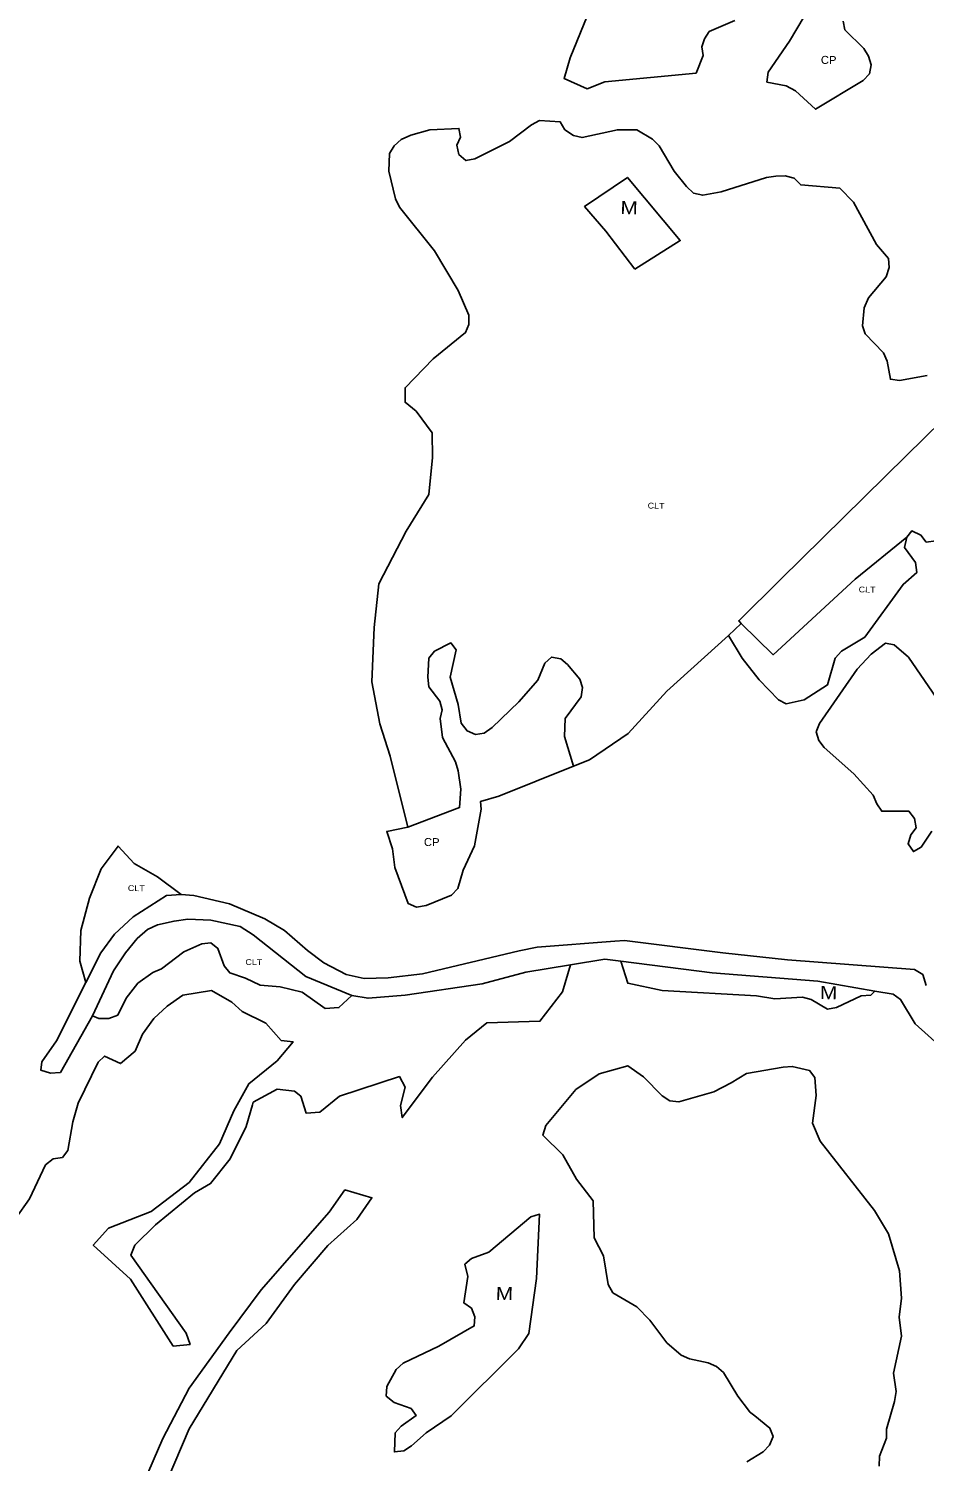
# Model space of a CAD drawing. Extents: x 713589 to 726391, y 7177764 to 7191819.
# Drawn here: x 716445 to 717161, y 7179057 to 7180202 of the extents above; entities that cross this region are included whole.
import ezdxf
from ezdxf.enums import TextEntityAlignment as Align

# ---------------------------------------------------------------- set-up
doc = ezdxf.new("R2010")
doc.units = 0
doc.header["$LTSCALE"] = 2.6
doc.layers.add('63', color=7, linetype='Continuous', lineweight=25)

msp = doc.modelspace()

# ---------------------------------------------------------------- linework, layer by layer
at = {"layer": '63'}
msp.add_line((717003.94, 7179716.98), (717014.24, 7179726.64), dxfattribs=at)
for points in [[(717009.07, 7180208.54), (716988.67, 7180199.99), (716984.72, 7180194.07), (716982.74, 7180187.48), (716983.73, 7180180.57), (716978.13, 7180166.59), (716905.26, 7180159.55), (716891.06, 7180153.97), (716872.6, 7180162.25), (716877.58, 7180178.73), (716891.16, 7180212.03)], [(717064.36, 7180211.82), (717052.84, 7180192.08), (717035.72, 7180167.4), (717034.64, 7180159.41), (717050.07, 7180156.31), (717057.64, 7180152.54), (717073.53, 7180137.76), (717111.73, 7180160.81), (717116.67, 7180166.07), (717117.99, 7180173.31), (717116.01, 7180180.22), (717112.07, 7180186.15), (717096.93, 7180201.28), (717095.62, 7180208.2)], [(717162.68, 7179924.84), (717140.63, 7179920.89), (717133.39, 7179921.88), (717130.76, 7179936.36), (717127.8, 7179942.94), (717113.32, 7179958.08), (717111.02, 7179964.67), (717112.42, 7179978.94), (717115.96, 7179987.04), (717130.11, 7180003.82), (717132.42, 7180011.06), (717131.76, 7180018.3), (717122.22, 7180029.49), (717103.8, 7180063.39), (717092.94, 7180074.58), (717061.68, 7180077.22), (717056.41, 7180082.48), (717049.17, 7180084.46), (717041.93, 7180084.13), (717034.37, 7180083.14), (716998.17, 7180071.63), (716983.36, 7180069), (716976.12, 7180070.65), (716970.52, 7180075.92), (716960.65, 7180088.09), (716948.48, 7180108.5), (716943.22, 7180113.76), (716930.72, 7180121.34), (716915.25, 7180121.34), (716886.95, 7180115.09), (716880.04, 7180116.74), (716873.13, 7180121.35), (716869.51, 7180127.6), (716853.06, 7180128.59), (716846.47, 7180125.3), (716829.03, 7180111.81), (716801.39, 7180097.99), (716794.15, 7180096.68), (716788.55, 7180101.62), (716786.91, 7180108.86), (716789.87, 7180115.44), (716788.56, 7180122.35), (716765.19, 7180121.36), (716750.05, 7180117.09), (716742.49, 7180113.47), (716736.89, 7180108.54), (716732.94, 7180102.28), (716732.61, 7180088.13), (716737.87, 7180066.09), (716741.16, 7180059.5), (716769.12, 7180024.62), (716787.88, 7179992.69), (716796.43, 7179972.95), (716796.43, 7179965.71), (716793.88, 7179959.1), (716767.99, 7179938.1), (716745.52, 7179915.05), (716745.5, 7179903.51), (716754.4, 7179896.23), (716767.23, 7179879.06), (716767.53, 7179859.27), (716764.51, 7179829.58), (716746.32, 7179800.25), (716724.48, 7179758.39), (716720.79, 7179723.43), (716719.07, 7179679.89), (716725.28, 7179646.24), (716733.49, 7179620.49), (716747.81, 7179563.73)], [(717217.73, 7179923.86), (717203.15, 7179916.93), (717145.88, 7179860.67), (717045.83, 7179761.97), (717045.8, 7179761.94), (717012.13, 7179728.72), (717014.24, 7179726.64)], [(717146.63, 7179795.56), (717150.5, 7179800.53), (717157.74, 7179797.24), (717162.02, 7179791.65), (717169.59, 7179792.63), (717171.89, 7179808.1), (717180.78, 7179829.16), (717181.11, 7179851.86), (717183.75, 7179859.1), (717190.66, 7179856.8), (717199.87, 7179844.95), (717207.77, 7179844.29), (717221.92, 7179848.24), (717243.97, 7179867.65), (717244.3, 7179875.54), (717240.35, 7179882.46), (717224.23, 7179898.25), (717216.01, 7179910.1), (717214.69, 7179917.01), (717217.73, 7179923.86)], [(717003.94, 7179716.98), (717014.91, 7179698.87), (717028.4, 7179681.43), (717043.86, 7179665.63), (717050.11, 7179662.34), (717064.59, 7179665.63), (717083.02, 7179677.47), (717089.28, 7179698.86), (717094.21, 7179704.45), (717112.97, 7179715.64), (717143.58, 7179757.76), (717154.44, 7179767.3), (717153.46, 7179775.19), (717144.58, 7179787.37), (717146.63, 7179795.56)], [(717014.24, 7179726.64), (717039.68, 7179701.53), (717105.27, 7179762.02), (717146.63, 7179795.56)], [(716747.81, 7179563.73), (716789.08, 7179579.32), (716790.03, 7179594.18), (716787.82, 7179608.75), (716785.92, 7179616.04), (716775.47, 7179635.36), (716773.57, 7179650.57), (716775.16, 7179657.54), (716773.26, 7179664.51), (716764.39, 7179675.92), (716763.76, 7179683.52), (716764.39, 7179698.72), (716769.14, 7179704.43), (716782.13, 7179711.08), (716786.25, 7179705.37), (716781.5, 7179683.52), (716787.83, 7179661.66), (716790.36, 7179646.77), (716795.11, 7179640.75), (716801.76, 7179637.89), (716808.73, 7179638.84), (716815.07, 7179643.28), (716836.3, 7179663.87), (716851.51, 7179681.29), (716857.21, 7179694.91), (716862.6, 7179699.66), (716869.88, 7179698.39), (716875.27, 7179693.64), (716885.09, 7179681.91), (716887.3, 7179675.26), (716886.35, 7179667.97), (716873.36, 7179650.55), (716873.04, 7179636.3), (716880.2, 7179612.48)], [(716880.2, 7179612.48), (716892.84, 7179617.55), (716923.72, 7179638.59), (716954.66, 7179672.48), (717003.94, 7179716.98)], [(717166.58, 7179560.64), (717158.03, 7179547.81), (717151.77, 7179544.19), (717147.5, 7179550.44), (717149.8, 7179557.68), (717154.08, 7179563.27), (717152.76, 7179570.51), (717148.16, 7179576.44), (717126.44, 7179576.44), (717122.49, 7179582.36), (717119.53, 7179589.28), (717104.07, 7179606.39), (717080.38, 7179627.45), (717076.1, 7179633.05), (717074.13, 7179639.96), (717076.76, 7179646.54), (717106.72, 7179689.97), (717117.91, 7179702.15), (717129.43, 7179710.7), (717136.34, 7179709.38), (717147.85, 7179699.51), (717173.51, 7179662.32)], [(716747.81, 7179563.73), (716747.72, 7179563.7), (716730.84, 7179560.31), (716735.54, 7179546.35), (716737.44, 7179531.46), (716747.88, 7179502.63), (716754.54, 7179499.78), (716762.46, 7179501.05), (716782.73, 7179509.28), (716787.8, 7179514.67), (716791.92, 7179529.24), (716801.11, 7179548.88), (716806.19, 7179578.02), (716805.66, 7179584.21), (716820.47, 7179588.5), (716880.2, 7179612.48)], [(716490.29, 7179439.59), (716485.56, 7179456.55), (716486.27, 7179481.08), (716493.27, 7179506.92), (716502.59, 7179530.43), (716516.2, 7179548.64), (716529.11, 7179534.7), (716547.65, 7179524.06), (716566.5, 7179509.91)], [(716490.29, 7179439.59), (716502.26, 7179463.36), (716513.31, 7179478.08), (716528.18, 7179492.13), (716554.95, 7179509.03), (716566.5, 7179509.91)], [(716566.5, 7179509.91), (716576.57, 7179509.05), (716605.27, 7179502.43), (716633.31, 7179490.43), (716649.08, 7179481.17), (716667.47, 7179465.22), (716680.47, 7179455.37), (716698.3, 7179445.92), (716712.77, 7179442.78), (716732, 7179443.19), (716759.55, 7179446.49), (716836.6, 7179464.8), (716851.05, 7179467.66), (716913.06, 7179472.44)], [(716495.65, 7179412.74), (716512.53, 7179448.87), (716522.18, 7179463.18), (716531.29, 7179474.63), (716539.62, 7179481.86), (716547.7, 7179485.53), (716560.9, 7179488.56), (716571.97, 7179490.11), (716590.15, 7179489.42), (716613.7, 7179484.32), (716624.09, 7179477.75), (716666.13, 7179444.22), (716702.92, 7179429.15)], [(716495.65, 7179412.74), (716500.66, 7179410.86), (716508.62, 7179410.85), (716515.91, 7179413.49), (716522.56, 7179427.06), (716531.86, 7179438.98), (716543.81, 7179447.58), (716550.77, 7179450.55), (716568.69, 7179464.11), (716582.95, 7179470.38), (716590.25, 7179471.36), (716595.87, 7179466.71), (716600.82, 7179452.78), (716605.45, 7179447.14), (716617.95, 7179443.05), (716629.62, 7179437.4), (716645.78, 7179436.05), (716663.26, 7179431.73), (716681.71, 7179418.84), (716692.6, 7179419.48), (716702.92, 7179429.15)], [(716913.06, 7179472.44), (716920.84, 7179473.04), (716999.45, 7179463.18), (717051.25, 7179457.51), (717152.61, 7179449.83), (717159.27, 7179445.79), (717161.91, 7179436.99)], [(716877.64, 7179453.64), (716905.13, 7179458.11), (716918.05, 7179456.46)], [(716918.05, 7179456.46), (716923.54, 7179438.89), (716950.91, 7179433.24), (717026.45, 7179428.82), (717040.9, 7179426.55), (717063.08, 7179427.82), (717070.05, 7179425.92), (717083.03, 7179418.31), (717090.32, 7179419.58), (717109.96, 7179428.76), (717117.88, 7179429.39), (717120.88, 7179432.71)], [(716918.05, 7179456.46), (716990.86, 7179447.15), (717075.45, 7179440.55), (717120.88, 7179432.71)], [(716877.64, 7179453.64), (716871.41, 7179432.05), (716853.28, 7179408.48), (716810.83, 7179407.35), (716793.72, 7179393.54), (716767.39, 7179363.92), (716743.26, 7179331.47), (716741.95, 7179341.22), (716745.6, 7179355.73), (716741, 7179364.31), (716693.14, 7179348.56), (716677.28, 7179335.72), (716666.4, 7179335.08), (716662.13, 7179348.61), (716657.19, 7179352.57), (716643.34, 7179354.25), (716624.19, 7179343.72), (716623.58, 7179341.63), (716618.55, 7179324.27), (716605.64, 7179298.56), (716590.1, 7179278.79), (716577.22, 7179271.23), (716546.17, 7179245.88), (716529.65, 7179229.41), (716526.34, 7179221.5), (716570.44, 7179159.08), (716573.72, 7179150.17), (716560.2, 7179148.87), (716525.98, 7179202.37), (716496.33, 7179229.47), (716508.56, 7179242.97), (716542.56, 7179256.44), (716572.95, 7179279.48), (716597.08, 7179310.45), (716608.67, 7179336.82), (716620.58, 7179358.57), (716643.37, 7179377.01), (716655.94, 7179392.16), (716646.37, 7179393.17), (716634.19, 7179407.04), (716615.4, 7179416.31), (716607.17, 7179423.91), (716590.85, 7179433.25), (716567.97, 7179429.31), (716555.36, 7179420.71), (716544.74, 7179410.79), (716535.77, 7179398.21), (716529.79, 7179384.63), (716518.17, 7179374.71), (716505.25, 7179380.69), (716500.27, 7179375.73), (716484.31, 7179342.95), (716479.98, 7179328.04), (716475.96, 7179305.18), (716471.65, 7179299.55), (716464.35, 7179298.57), (716458.05, 7179293.61), (716445.41, 7179266.46), (716423.49, 7179235.67)], [(716702.92, 7179429.15), (716715.89, 7179426.95), (716745.64, 7179429.34), (716807.24, 7179438.54), (716842.11, 7179447.86), (716877.64, 7179453.64)], [(716469.95, 7179367.44), (716462.07, 7179366.94), (716454.4, 7179369.44), (716454.4, 7179369.46), (716455.32, 7179375.99), (716466.84, 7179393.01), (716490.29, 7179439.59)], [(717120.88, 7179432.71), (717135.69, 7179430.15), (717141.47, 7179426.04), (717153.05, 7179406.54), (717176.7, 7179385.5)], [(716469.95, 7179367.44), (716470.06, 7179367.45), (716495.65, 7179412.74)], [(716895.78, 7179264.91), (716882.48, 7179282.34), (716871.71, 7179301.66), (716855.56, 7179317.51), (716858.1, 7179325.11), (716881.86, 7179353.93), (716900.55, 7179366.39), (716923.43, 7179372.98), (716935.95, 7179364.05), (716951.1, 7179348.85), (716957.03, 7179344.89), (716964.29, 7179344.21), (716992.34, 7179352.08), (717006.21, 7179359.32), (717018.47, 7179366.84), (717047.76, 7179371.77), (717055, 7179372.43), (717068.82, 7179369.14), (717073.09, 7179363.54), (717074.08, 7179349.06), (717071.11, 7179327.01), (717077.36, 7179312.53), (717120.79, 7179257.24), (717131.98, 7179238.48), (717140.53, 7179208.87), (717142.17, 7179187.15), (717140.52, 7179172.01), (717142.16, 7179156.87), (717135.9, 7179127.26), (717137.88, 7179112.45), (717136.56, 7179104.55), (717130.3, 7179082.51), (717130.3, 7179075.27), (717124.7, 7179060.79), (717124.37, 7179052.89)], [(716496.31, 7178946.16), (716551.87, 7179074.99), (716573.01, 7179115.2), (716605.05, 7179159.36), (716630.46, 7179193.82), (716684.85, 7179256.01), (716697.38, 7179273.74), (716719.06, 7179267.36), (716706.83, 7179249.9), (716683.7, 7179229.16), (716657.26, 7179198.19), (716634.45, 7179166.89), (716610.99, 7179145.16), (716572.95, 7179082.54), (716537.85, 7179000.13)], [(717018.66, 7179056.38), (717031.65, 7179064.3), (717036.72, 7179069.68), (717039.57, 7179076.65), (717037.04, 7179083.3), (717025.02, 7179093.07), (717020.89, 7179096.36), (717020.76, 7179096.53), (717011.38, 7179108.71), (716999.98, 7179127.72), (716994.28, 7179132.48), (716987.63, 7179135.33), (716972.74, 7179138.5), (716966.09, 7179141.67), (716954.69, 7179151.49), (716941.07, 7179169.55), (716930.62, 7179180.32), (716911.61, 7179191.41), (716907.81, 7179198.07), (716904.01, 7179220.88), (716896.73, 7179235.45), (716895.78, 7179264.91)]]:
    msp.add_lwpolyline(points, dxfattribs=at)
for points in [[(716929.11, 7180009.96), (716965.43, 7180032.66), (716923.18, 7180083.14), (716888.95, 7180059.84), (716906.07, 7180040.35)], [(716737.67, 7179079.41), (716737.04, 7179064.2), (716744.64, 7179065.15), (716750.66, 7179068.95), (716762.38, 7179079.4), (716782.34, 7179093.02), (716836.21, 7179146.55), (716844.44, 7179158.9), (716850.47, 7179202.93), (716853.01, 7179254.25), (716846.05, 7179252.04), (716812.46, 7179223.85), (716798.52, 7179218.78), (716793.35, 7179214.22), (716795.67, 7179204.53), (716792.5, 7179183.3), (716798.51, 7179179.18), (716801.36, 7179172.21), (716800.73, 7179164.93), (716772.53, 7179148.78), (716744.02, 7179135.16), (716738.32, 7179130.09), (716731.03, 7179116.47), (716730.39, 7179108.87), (716736.73, 7179103.8), (716750.35, 7179099.04), (716754.47, 7179093.34), (716742.43, 7179084.79)]]:
    msp.add_lwpolyline(points, close=True, dxfattribs=at)

# ---------------------------------------------------------------- texts
for s, height, width, p in [('CP', 6.4, 1.05, (717084, 7180173.91)), ('M', 10.4, 1.2, (716924.5, 7180053.81)), ('CLT', 4.64, 1.15, (716946.1, 7179818.39)), ('CLT', 4.64, 1.15, (717114.73, 7179751.35)), ('CP', 6.4, 1.05, (716766.76, 7179548.59)), ('CLT', 4.64, 1.15, (716530.66, 7179512.57)), ('CLT', 4.64, 1.15, (716624.62, 7179453.49)), ('M', 10.4, 1.2, (717083.92, 7179426.14)), ('M', 10.4, 1.2, (716824.86, 7179185.65))]:
    msp.add_text(s, height=height, rotation=359.062, dxfattribs=dict(at, width=width)).set_placement(p, align=Align.CENTER)

doc.saveas('drawing.dxf')
